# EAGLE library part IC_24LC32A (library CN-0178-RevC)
Microchip 32K I2C Serial EEPROM; P/N 24LC32A-I/SN
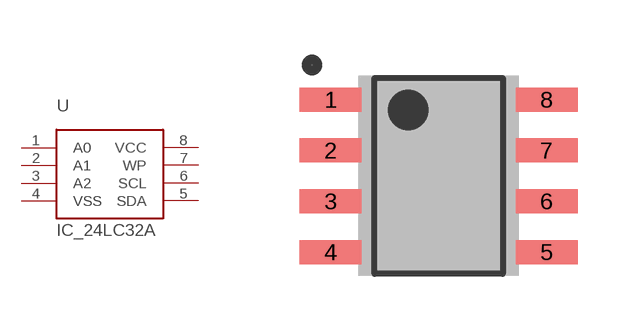
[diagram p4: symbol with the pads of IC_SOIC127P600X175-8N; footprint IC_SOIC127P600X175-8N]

Designator prefix U

## IC_24LC32A_SOIC8  [IC_SOIC127P600X175-8N]
1  A0  pas
2  A1  pas
3  A2  pas
4  VSS  pas
5  SDA  pas
6  SCL  pas
7  WP  pas
8  VCC  pas

## Footprint IC_SOIC127P600X175-8N (pad centres in mm)
(SOIC-8) 1.27mm pitch; 3.90mm W X 4.90mm L X 1.75mm H body; JEDEC MS-012AA
smd 1.55 x 0.6: 1 -2.7,1.905; 2 -2.7,0.635; 3 -2.7,-0.635; 4 -2.7,-1.905; 5 2.7,-1.905; 6 2.7,-0.635; 7 2.7,0.635; 8 2.7,1.905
